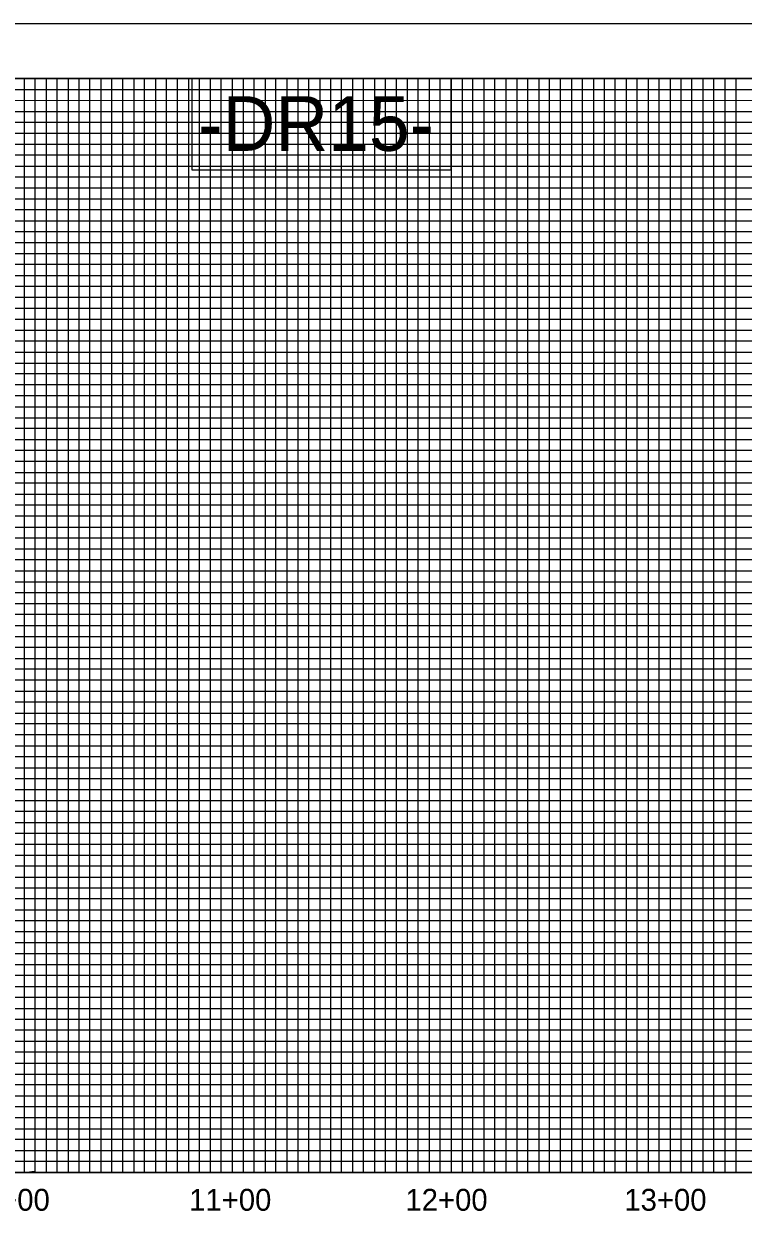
# Model space of a CAD drawing. Extents: x 505602 to 507286, y 483109 to 484209.
# Drawn here: x 506624 to 506952, y 483662 to 484209 of the extents above; entities that cross this region are included whole.
import ezdxf

# ---------------------------------------------------------------- set-up
doc = ezdxf.new("R2010")
doc.units = 0
for name, color, linetype in [('Exist Vertical Profile Vertical Axis Label', 7, 'Continuous'), ('Old_Level_1', 7, 'Continuous'), ('Prop Grid Mask', 7, 'Continuous'), ('Sheet Layout Profile Border Port 2', 7, 'Continuous'), ('Sheet Plot Border Outside CELL', 7, 'Continuous'), ('Sheet Profile CELL', 7, 'Continuous'), ('Sheet Profile Grid Major CELL', 7, 'Continuous'), ('Sheet Profile Grid Middle CELL', 7, 'Continuous'), ('Sheet Profile Grid Minor CELL', 7, 'Continuous')]:
    doc.layers.add(name, color=color, linetype=linetype)

msp = doc.modelspace()

# ---------------------------------------------------------------- linework, layer by layer
at = {"layer": 'Prop Grid Mask'}
msp.add_lwpolyline([(506819.08, 484183.71), (506700.61, 484183.71), (506700.61, 484142), (506819.08, 484142)], close=True, dxfattribs=at)
at = {"layer": 'Sheet Layout Profile Border Port 2'}
msp.add_lwpolyline([(506569.08, 484183.71), (507069.08, 484183.71), (507069.08, 483683.71), (506569.08, 483683.71)], close=True, dxfattribs=at)
at = {"layer": 'Sheet Plot Border Outside CELL'}
msp.add_lwpolyline([(505602.08, 483108.71), (507286.08, 483108.71), (507286.08, 484208.71), (505602.08, 484208.71)], close=True, dxfattribs=at)
at = {"layer": 'Sheet Profile CELL'}
msp.add_line((505769.08, 483683.71), (507269.08, 483683.71), dxfattribs=at)
msp.add_lwpolyline([(507269.08, 484183.71), (505769.08, 484183.71), (505769.08, 483133.71), (507269.08, 483133.71)], close=True, dxfattribs=at)
at = {"layer": 'Sheet Profile Grid Major CELL'}
for points in [[(506619.08, 483683.71), (506669.08, 483683.71), (506669.08, 484183.71), (506719.08, 484183.71), (506719.08, 483683.71), (506769.08, 483683.71), (506769.08, 484183.71), (506819.08, 484183.71), (506819.08, 483683.71), (506869.08, 483683.71), (506869.08, 484183.71), (506919.08, 484183.71), (506919.08, 483683.71), (506969.08, 483683.71), (506969.08, 484183.71), (507019.08, 484183.71), (507019.08, 483683.71), (507069.08, 483683.71), (507069.08, 484183.71), (507095.38, 484183.71)], [(505769.08, 484133.71), (507069.08, 484133.71)], [(507069.08, 484083.71), (505769.08, 484083.71), (505769.08, 484033.71), (507069.08, 484033.71)], [(507269.08, 483983.71), (505769.08, 483983.71), (505769.08, 483933.71), (507269.08, 483933.71)], [(507269.08, 483883.71), (505769.08, 483883.71), (505769.08, 483833.71), (507269.08, 483833.71)], [(507269.08, 483783.71), (505769.08, 483783.71), (505769.08, 483783.71), (505769.08, 483733.71), (507269.08, 483733.71)]]:
    msp.add_lwpolyline(points, dxfattribs=at)
at = {"layer": 'Sheet Profile Grid Middle CELL'}
msp.add_line((505769.08, 484158.71), (507069.03, 484158.71), dxfattribs=at)
msp.add_line((505769.08, 484158.71), (507069.03, 484158.71), dxfattribs=at)
for points in [[(506594.08, 484183.71), (506644.08, 484183.71), (506644.08, 483683.71), (506694.08, 483683.71), (506694.08, 484183.71), (506744.08, 484183.71), (506744.08, 483683.71), (506794.08, 483683.71), (506794.08, 484183.71), (506844.08, 484183.71), (506844.08, 483683.71), (506894.08, 483683.71), (506894.08, 484183.71), (506944.08, 484183.71), (506944.08, 483683.71), (506994.08, 483683.71), (506994.08, 484183.71), (507044.08, 484183.71), (507044.08, 483683.71), (507094.08, 483683.71), (507094.08, 484022.66)], [(507069.08, 484108.71), (505769.08, 484108.71), (505769.08, 484058.71), (507069.08, 484058.71)], [(507269.08, 484008.71), (505769.08, 484008.71), (505769.08, 483958.71), (507094.08, 483958.71)], [(507269.08, 483908.71), (505769.08, 483908.71), (505769.08, 483858.71), (507269.08, 483858.71)], [(507269.08, 483808.71), (505769.08, 483808.71), (505769.08, 483758.71), (507269.08, 483758.71)], [(507269.08, 483708.71), (505769.08, 483708.71)]]:
    msp.add_lwpolyline(points, dxfattribs=at)
at = {"layer": 'Sheet Profile Grid Minor CELL'}
for p, q in [((505819.08, 484178.71), (507069.08, 484178.71)), ((507069.08, 484173.71), (505819.08, 484173.36)), ((505819.08, 484168.71), (507069.08, 484168.71)), ((507069.03, 484048.71), (505819.08, 484048.71)), ((507069.08, 484043.71), (505819.08, 484043.71)), ((507069.08, 484038.71), (505819.08, 484038.71)), ((505819.08, 484028.71), (507069.08, 484028.71)), ((507069.08, 484023.71), (505819.08, 484023.71)), ((505819.08, 484018.71), (507219.08, 484018.71)), ((507219.08, 483998.71), (505819.08, 483998.71)), ((505819.08, 483993.71), (507219.08, 483993.71)), ((507219.08, 483973.71), (505819.08, 483973.71)), ((505819.08, 483968.71), (507219.08, 483968.71)), ((507219.08, 483948.71), (505819.08, 483948.71)), ((505819.08, 483943.71), (507219.08, 483943.71)), ((507219.08, 483938.71), (505819.08, 483938.71)), ((505819.08, 483928.71), (507219.08, 483928.71)), ((507219.08, 483923.71), (505819.08, 483923.71)), ((505819.08, 483918.71), (507219.08, 483918.71)), ((507219.08, 483913.71), (505819.08, 483913.71)), ((505819.08, 483903.71), (507219.08, 483903.71)), ((507219.08, 483898.71), (505819.08, 483898.71)), ((505819.08, 483893.71), (507219.08, 483893.71)), ((507219.08, 483888.71), (505819.08, 483888.71)), ((505819.08, 483878.71), (507219.08, 483878.71)), ((507219.08, 483873.71), (505819.08, 483873.71)), ((505819.08, 483868.71), (507219.08, 483868.71)), ((507219.08, 483863.71), (505819.08, 483863.71)), ((505819.08, 483853.71), (507219.08, 483853.71)), ((507219.08, 483848.71), (505819.08, 483848.71)), ((505819.08, 483843.71), (507219.08, 483843.71)), ((507219.08, 483838.71), (505819.08, 483838.71)), ((505819.08, 483828.71), (507219.08, 483828.71)), ((507219.08, 483823.71), (505819.08, 483823.71)), ((505819.08, 483818.71), (507219.08, 483818.71)), ((507219.08, 483813.71), (505819.08, 483813.71)), ((505819.08, 483803.71), (507219.08, 483803.71)), ((507219.08, 483798.71), (505819.08, 483798.71)), ((507219.08, 483793.71), (505819.08, 483793.71)), ((507219.08, 483788.71), (505819.08, 483788.71)), ((505819.08, 483778.71), (507219.08, 483778.71)), ((507219.08, 483773.71), (505819.08, 483773.71)), ((505819.08, 483768.71), (507219.08, 483768.71)), ((507219.08, 483763.71), (505819.08, 483763.71)), ((505819.08, 483753.71), (507219.08, 483753.71)), ((507219.08, 483748.71), (505819.08, 483748.71)), ((505819.08, 483743.71), (507219.08, 483743.71)), ((507219.08, 483738.71), (505819.08, 483738.71)), ((505819.08, 483728.71), (507219.08, 483728.71)), ((507219.08, 483723.71), (505819.08, 483723.71)), ((505819.08, 483718.71), (507219.08, 483718.71)), ((507219.08, 483713.71), (505819.08, 483713.71)), ((505819.08, 483703.71), (507219.08, 483703.71)), ((507219.08, 483698.71), (505819.08, 483698.71)), ((505819.08, 483693.71), (507219.08, 483693.71))]:
    msp.add_line(p, q, dxfattribs=at)
for points in [[(506614.08, 484183.71), (506624.08, 484183.71), (506624.08, 483683.71), (506628.78, 483684.26), (506629.08, 483683.71), (506629.08, 484183.71), (506634.08, 484183.71), (506634.08, 483683.71), (506639.08, 483683.71), (506639.08, 484183.71), (506649.08, 484183.71), (506649.08, 483683.71), (506654.08, 483683.71)], [(506654.08, 483683.71), (506654.08, 484183.71), (506659.08, 484183.71), (506659.08, 483683.71), (506664.08, 483683.71), (506664.08, 484183.71), (506674.08, 484183.71), (506674.08, 483683.71), (506679.08, 483683.71), (506679.08, 484183.71), (506684.08, 484183.71), (506684.08, 483683.71), (506689.08, 483683.71), (506689.08, 484183.71), (506699.08, 484183.71), (506699.08, 483683.71), (506704.08, 483683.71), (506704.08, 484183.71), (506709.08, 484183.71), (506709.08, 483683.71), (506714.08, 483683.71), (506714.08, 484183.71), (506724.08, 484183.71), (506724.08, 483683.71), (506729.08, 483683.71), (506729.08, 484183.71), (506734.08, 484183.71), (506734.08, 483683.71), (506739.08, 483683.71), (506739.08, 484183.71), (506749.08, 484183.71), (506749.08, 483683.71), (506754.08, 483683.71), (506754.08, 484183.71), (506759.08, 484183.71), (506759.08, 483683.71), (506764.08, 483683.71), (506764.08, 484183.71), (506774.08, 484183.71), (506774.08, 483683.71), (506779.08, 483683.71), (506779.08, 484183.71), (506784.08, 484183.71), (506784.08, 483683.71), (506789.08, 483683.71), (506789.08, 484183.71), (506799.08, 484183.71), (506799.08, 483683.71), (506804.08, 483683.71), (506804.08, 484183.71), (506809.08, 484183.71), (506809.08, 483683.71), (506814.08, 483683.71), (506814.08, 484183.71), (506824.08, 484183.71), (506824.08, 483683.71), (506829.08, 483683.71), (506829.08, 484183.71), (506834.08, 484183.71), (506834.08, 483683.71), (506839.08, 483683.71), (506839.08, 484183.71), (506849.08, 484183.71), (506849.08, 483683.71), (506854.08, 483683.71), (506854.08, 484183.71), (506859.08, 484183.71), (506859.08, 483683.71), (506864.08, 483683.71), (506864.08, 484183.71), (506874.08, 484183.71), (506874.08, 483683.71), (506879.08, 483683.71), (506879.08, 484183.71), (506884.08, 484183.71), (506884.08, 483683.71), (506889.08, 483683.71), (506889.08, 484183.71), (506899.08, 484183.71), (506899.08, 483683.71), (506904.08, 483683.71), (506904.08, 484183.71), (506909.08, 484183.71), (506909.08, 483683.71), (506914.08, 483683.71), (506914.08, 484183.71), (506924.08, 484183.71), (506924.08, 483683.71), (506929.08, 483683.71), (506929.08, 484183.71), (506934.08, 484183.71), (506934.08, 483683.71), (506939.08, 483683.71), (506939.08, 484183.71), (506949.08, 484183.71), (506949.08, 483683.71), (506954.08, 483683.71)], [(507069.08, 484163.71), (505819.08, 484163.71), (505819.08, 484153.71), (507069.08, 484153.71)], [(507069.03, 484148.71), (505819.08, 484148.71), (505819.08, 484143.71), (507069.08, 484143.71)], [(507069.08, 484138.71), (505819.08, 484138.71), (505819.08, 484128.71), (507069.08, 484128.71)], [(507069.08, 484123.71), (505819.08, 484123.71), (505819.08, 484118.71), (507069.08, 484118.71)], [(507069.08, 484113.71), (505819.08, 484113.71), (505819.08, 484103.71), (507069.08, 484103.71)], [(507069.08, 484098.71), (505819.08, 484098.71), (505819.08, 484093.71), (507069.08, 484093.71)], [(507069.08, 484088.71), (505819.08, 484088.71), (505819.08, 484078.71), (507069.08, 484078.71)], [(507069.08, 484073.61), (505819.18, 484073.61), (505819.18, 484068.71), (507069.08, 484068.71)], [(507069.08, 484063.71), (505819.08, 484063.71), (505819.08, 484053.71), (507069.08, 484053.71)], [(507219.08, 484013.71), (505819.08, 484013.71), (505819.08, 484003.71), (507219.08, 484003.71)], [(507219.08, 483988.71), (505819.08, 483988.71), (505819.08, 483978.71), (507219.08, 483978.71)], [(507219.08, 483963.71), (505819.08, 483963.71), (505819.08, 483953.71), (507219.08, 483953.71)], [(507219.08, 483688.71), (505819.08, 483688.71)]]:
    msp.add_lwpolyline(points, dxfattribs=at)

# ---------------------------------------------------------------- texts
at = {"layer": 'Exist Vertical Profile Vertical Axis Label'}
for s, p in [('10+00', (506598.21, 483666.21)), ('11+00', (506699.41, 483666.21)), ('12+00', (506798.21, 483666.21)), ('13+00', (506898.21, 483666.21))]:
    msp.add_text(s, height=10, dxfattribs=at).set_placement(p)
at = {"layer": 'Old_Level_1'}
msp.add_text('-DR15-', height=25, dxfattribs=at).set_placement((506703.53, 484150.68))

doc.saveas('drawing.dxf')
